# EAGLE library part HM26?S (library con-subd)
SUB-D
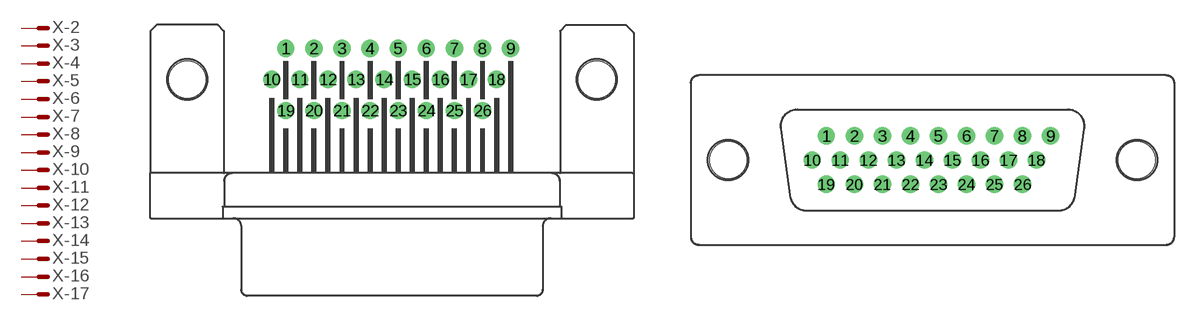
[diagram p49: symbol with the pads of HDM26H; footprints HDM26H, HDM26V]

Designator prefix X; gates -2=M -3=M -4=M -5=M -6=M -7=M -8=M -9=M -10=M -11=M -12=M -13=M -14=M -15=M -16=M -17=M -18=M -19=M -20=M -21=M -22=M -23=M -24=M -25=M -26=M -1=MV

## HM26HS (OC_FARNELL: unknown; OC_NEWARK: unknown)  [HDM26H]
1  -1:M  pas
2  -2:M  pas
3  -3:M  pas
4  -4:M  pas
5  -5:M  pas
6  -6:M  pas
7  -7:M  pas
8  -8:M  pas
9  -9:M  pas
10  -10:M  pas
11  -11:M  pas
12  -12:M  pas
13  -13:M  pas
14  -14:M  pas
15  -15:M  pas
16  -16:M  pas
17  -17:M  pas
18  -18:M  pas
19  -19:M  pas
20  -20:M  pas
21  -21:M  pas
22  -22:M  pas
23  -23:M  pas
24  -24:M  pas
25  -25:M  pas
26  -26:M  pas

## HM26VS (OC_FARNELL: unknown; OC_NEWARK: unknown)  [HDM26V]
Pads as for HDM26H

## Footprint HDM26H (pad centres in mm)
SUB-D
drill 0.9 round: 1 -8.639,2.54; 2 -6.353,2.54; 3 -4.067,2.54; 4 -1.781,2.54; 5 0.505,2.54; 6 2.791,2.54; 7 5.077,2.54; 8 7.363,2.54; 9 9.649,2.54; 10 -9.782,0; 11 -7.496,0; 12 -5.21,0; 13 -2.924,0; 14 -0.638,0; 15 1.648,0; 16 3.934,0; 17 6.22,0; 18 8.506,0; 19 -8.639,-2.54; 20 -6.353,-2.54; 21 -4.067,-2.54; 22 -1.781,-2.54; 23 0.505,-2.54; 24 2.791,-2.54; 25 5.077,-2.54; 26 7.363,-2.54
hole 3 at -16.65,0
hole 3 at 16.65,0

## Footprint HDM26V (pad centres in mm)
SUB-D
drill 0.9 round: 1 -8.658,1.98; 2 -6.372,1.98; 3 -4.086,1.98; 4 -1.8,1.98; 5 0.486,1.98; 6 2.772,1.98; 7 5.058,1.98; 8 7.344,1.98; 9 9.63,1.98; 10 -9.801,0; 11 -7.515,0; 12 -5.229,0; 13 -2.943,0; 14 -0.657,0; 15 1.629,0; 16 3.915,0; 17 6.201,0; 18 8.487,0; 19 -8.658,-1.98; 20 -6.372,-1.98; 21 -4.086,-1.98; 22 -1.8,-1.98; 23 0.486,-1.98; 24 2.772,-1.98; 25 5.058,-1.98; 26 7.344,-1.98
hole 3 at -16.65,0
hole 3 at 16.65,0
